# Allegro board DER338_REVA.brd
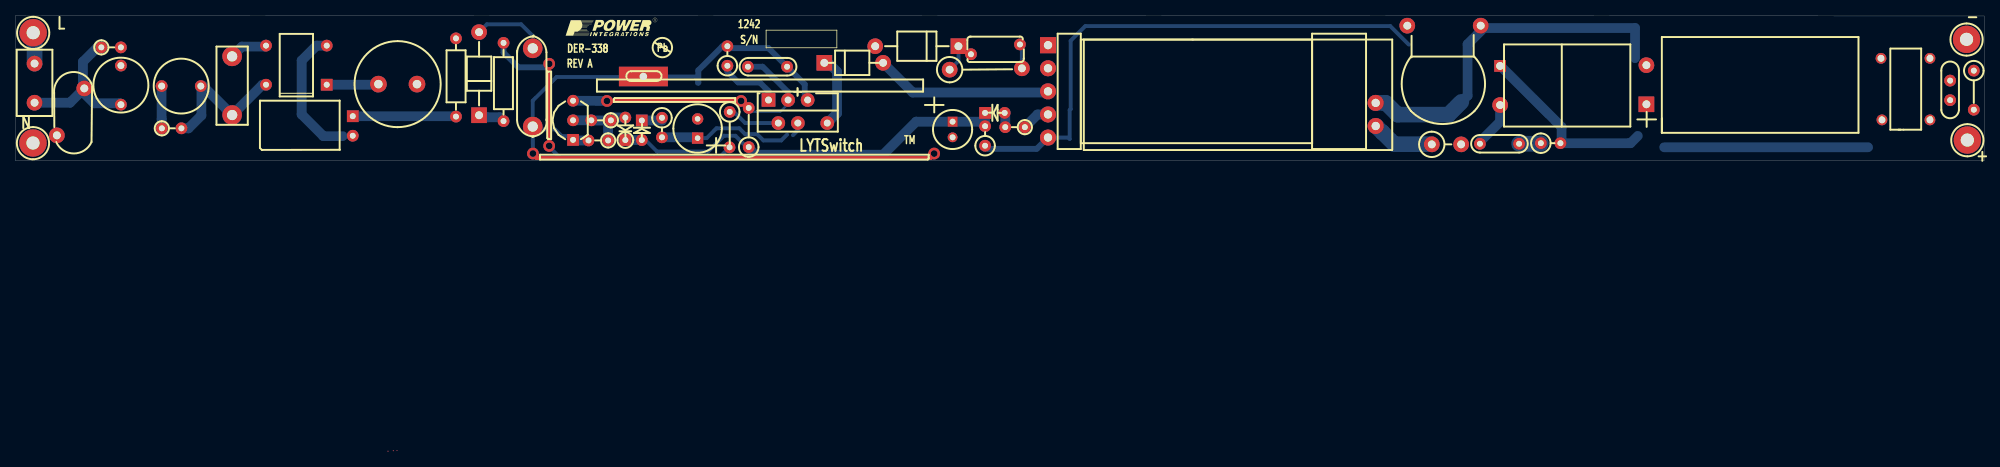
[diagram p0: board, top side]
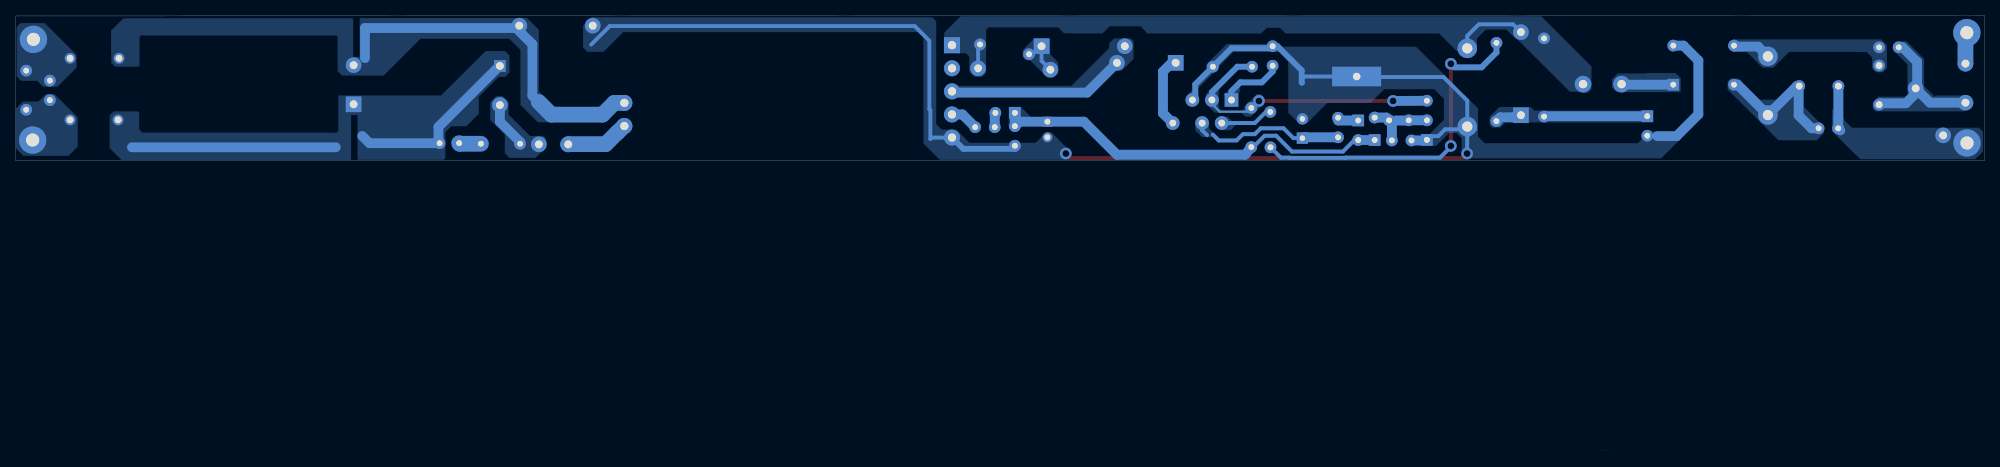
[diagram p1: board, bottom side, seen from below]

Outline 255.41 x 18.84 mm; copper layers: TOP, BOTTOM. Coordinates in mm from the lower left corner of the outline.
Outline path: 0.02,0 0,18.84 255.37,18.76 255.41,0 0.02,0 ; 0.02,0 0.04,0 0.02,0

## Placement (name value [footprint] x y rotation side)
BR1  DF06M  [PIDAXBRIDGEDFM]  40.4 9.86 270 top
C1  33 nF  [PI_NP_CAP400X160LS300D040]  28.11 13.51 270 top
C2  1 uF  [PIPOLCAPCYLD250LS100030]  43.76 5.74 270 top
C3  100 nF  [PINPCAPRAD500X260400040]  67.07 14.58 270 top
C4  2.2 nF  [PINPCAPRAD290X160250030]  130.29 15.06 180 top
C5  100 nF  [PINPCAPRAD200X100200030]  95.01 12.17 0 top
C6  47 uf  [PIPOLCAPCLYD248LS098028]  88.49 4.14 90 top
C7  10 uF  [PIPOLCAPCLYD200LS80030]  121.56 5.03 270 top
C8  2.2 nF  [PINPYCAPRAD540X290LS400040]  190.06 17.5 180 top
C9  150 pF  [PINPCAPRAD250X100200030]  195.04 2.16 180 top
C10  330 uF  [PIPOLCAPCLYD500LS2000401000LH]  211.55 7.29 90 top
C11  100 nF  [PINPCAPRAD200X100100030]  250.94 7.82 90 top
D1  1N4007  [PIDV200X110X040DO41]  60.14 5.87 90 top
D2  BYV26B  [PIDAX425X150040SOD57]  122.32 14.83 180 top
D3  UF4004  [PIDV200X110X040DO41#2]  103.78 12.67 0 top
D4  BAV21  [PIDV200X080X030DO35]  125.77 6.17 0 top
D5  1N4148  [PIDV200X080X030DO35]  81.25 5.18 270 top
D6  LQA06T300  [PI_TO220]  192.57 12.27 180 top
F1  3.15 A  [PI_RST_MICROFUSE]  2.48 12.57 270 top
HS1  HEATSINK,FAB, eSIP WITH BRKTS, DER318, PI CUST  [PI_HS_DER318_ESIP]  75.43 8.94 0 top
J1  CON1  [PITPKEYSTONE125X125]  2.3 16.59 0 top
J2  CON1  [PITPKEYSTONE125X125]  2.28 2.26 0 top
J3  CON1  [PITPKEYSTONE125X125]  253.18 2.64 0 top
J4  CON1  [PITPKEYSTONE125X125]  253.08 15.72 0 top
L1  1 mH  [PICHOKE030DIALS200035]  13.68 7.24 90 top
L2  1 mH  [PICHOKE030DIALS200035]  18.97 9.65 0 top
L3  470 uH  [PI_CHOKE_TOK441LS197D043]  47.08 9.91 0 top
L4  Ferrite Bead (3.5 x 4.45 mm)  [PI12WVRESD180LS150D040#2]  183.71 2.08 0 top
L5  100uH  [PI_TOROID_CM_CHOKE_4P]  238.04 3.1 0 top
NOREF  -  []  0.02 0.03 90 top
NOREF#2  -  []  0.02 0 0 top
NOREF#3  -  []  -244.17 -145.45 0 top
NOREF#4  -  []  -12.51 -112.42 0 top
NOREF#5  -  []  71.37 16.13 0 top
Q1  2N3904  [PITO92R100]  72.33 2.67 90 top
R1  5.1 k  [PI18WVRESD80LS100D030]  11.14 14.68 0 top
R2  5.1 k  [PI18WVRESD80LS100D030]  18.99 4.17 0 top
R4  200 k  [PI12WVRESD180LS150D040]  121.18 11.79 0 top
R5  1.5 M  [PI14WRESD100LS500D030]  63.31 5.11 90 top
R6  604 k  [PI14WVRESD100LS200D030]  92.65 6.3 270 top
R8  5.1 k  [PI14WVRESD100LS100D030]  83.86 5.54 270 top
R9  24.9 k  [PI14WVRESD100LS100D030]  92.35 12.29 90 top
R10  130 k  [PI14WVRESD100LS100D030#3]  95.11 1.73 90 top
R11  10 k  [PI14WVRESD100LS100D030]  125.77 1.91 90 top
R12  4.7 k  [PI18WVRESD80LS100D030]  76.88 2.59 180 top
R13  51  [PI18WVRESD80LS100D030]  130.93 4.32 180 top
R14  47  [PI14WVRESD100LS100D030]  197.86 2.24 0 top
R15  20 k  [PI14WVRESD100LS100D030#3]  254.02 11.66 270 top
R16  510 k  [PI14WVRESD100LS100D030#2]  57.14 15.85 270 top
R17  100  [PI18WVRESD80LS100D030]  77.23 5.21 180 top
RV1  140 Vac  [PIDISC350X225LS240X140040]  8.93 9.35 270 top
T1  EDR2810  [PI_BOBBIN_EDR2810_9P]  155.19 8.97 0 top
U1  LYT4215E  [PIICESIP76TH]  97.68 7.85 0 top
VR1  1N5256B  [PIDV200X080X030DO35#2]  79.11 2.64 90 top

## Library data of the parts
BR1 = DIODE BRIDGE_+-~~
C1 C3-C5 C9 C11 = CAP NP
C2 = CAP POL: alternate symbols: (pipolcapcyld250ls100030h)
C6 = CAP POL
C7 = CAP POL: alternate symbols: (pipolcapclyd200ls80030h)
C8 = CAP NP: alternate symbols: (pinpycaprad540x290ls400040h)
C10 = CAP POL: alternate symbols: (pipolcapclyd500ls2000401000lh)
D1 = DIODE: alternate symbols: (pidax475x125040do41,pidv200x110x040do41wbead,pidax390x125040do41)
D2 = DIODE: alternate symbols: (pidax425x150040sod57)
D3 = DIODE: alternate symbols: (pidax475x125040do41,pidax390x125040do41)
D4 D5 = DIODE: alternate symbols: (pidax375x070030do35,pidv100x080x030do35)
D6 = DIODE: alternate symbols: (PI_TO220)
F1 = FUSE
HS1 = HS-PI_CUSTOM
J1-J4 = TESTPOINT
L1-L4 = INDUCTOR
L5 = INDUCTOR_4P
Q1 = NPN_EBC: alternate symbols: (PIT092100)
R1 R2 = R: alternate symbols: (pi18wresd080ls300d030); tolerance: 5%
R4 = R: alternate symbols: (pi12wvresd180ls200d040,pi12wvresd180ls250d040,pi12wresd180ls675d040)
R5 R8 R11 R15 = R: alternate symbols: (pi14wvresd100ls200d030,pi14wresd100ls400d030,pi14wresd100ls500d030); tolerance: 5%
R6 R10 R14 R16 = R: alternate symbols: (pi14wvresd100ls200d030,pi14wresd100ls400d030,pi14wresd100ls500d030)
R9 = R: alternate symbols: (pi14wvresd100ls200d030,pi14wresd100ls400d030,pi14wresd100ls500d030); tolerance: 1%
R12 R13 R17 = R: alternate symbols: (pi18wresd080ls300d030)
RV1 = VARISTOR
T1 = BEDR2810_H_9P
U1 = LNK40X_eSIP
VR1 = DIODE_ZENER: alternate symbols: (pidax375x070030do35)

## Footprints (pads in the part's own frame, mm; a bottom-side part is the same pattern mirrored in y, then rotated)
PI12WVRESD180LS150D040
  round 2.032 hole 1.016: 1(0,0) 2(9.373,0.178)
PI12WVRESD180LS150D040#2
  round 2.032 hole 1.016: 1(0,0) 2(3.81,0)
PI14WRESD100LS500D030
  round 1.524 hole 0.762: 1(0,0) 2(10.16,0)
PI14WVRESD100LS100D030
  round 1.524 hole 0.762: 1(0,0) 2(2.54,0)
PI14WVRESD100LS100D030#2
  round 1.524 hole 0.762: 1(0,0) 2(10.16,0)
PI14WVRESD100LS100D030#3
  round 1.524 hole 0.762: 1(0,0) 2(5.08,0)
PI14WVRESD100LS200D030
  round 1.524 hole 0.762: 1(0,0) 2(4.597,-0.025)
PI18WVRESD80LS100D030
  round 1.524 hole 0.762: 1(0,0) 2(2.54,0)
PI_BOBBIN_EDR2810_9P
  rect 2.083x2.083 hole 1.067: 1(-21.25,5.999)
  round 2.083 hole 1.067: 2(-21.25,3) 3(-21.25,0) 4(-21.25,-3) 5(-21.25,-5.999) 6(21.25,-4.501) 7(21.25,-1.501)
  round 0.127 smd: 8(-106.172,-46.685) 9(-106.858,-46.736)
PI_CHOKE_TOK441LS197D043
  round 2.159 hole 1.092: 1(0,0) 2(5.001,0)
PI_HS_DER318_ESIP
  rect 6.35x2.54 hole 0.965: 1(6.02,1.956)
PI_NP_CAP400X160LS300D040
  round 2.54 hole 1.321: 1(0,0) 2(7.62,0)
PI_RST_MICROFUSE
  round 2.032 hole 1.016: 1(0,0) 2(5.08,0)
PI_TO220
  round 0.127 smd: (143.078,49.962)
  rect 1.524x1.524 hole 1.016: 1(0,0)
  round 2.032 hole 1.016: 2(0,5.08)
PI_TOROID_CM_CHOKE_4P
  round 1.397 hole 0.889: 1(4.064,2.159) 2(10.287,2.159) 3(10.287,10.16) 4(3.937,10.16)
PICHOKE030DIALS200035
  round 1.524 hole 0.889: 1(0,0) 2(5.08,0)
PIDAX425X150040SOD57
  rect 2.032x2.032 hole 1.016: 1(0,0)
  round 2.032 hole 1.016: 2(10.795,0)
PIDAXBRIDGEDFM
  rect 1.524x1.524 hole 0.762: 1(0.025,-0.025)
  round 1.524 hole 0.762: 2(-5.055,-0.025) 3(0.025,-7.899) 4(-5.055,-7.899)
PIDISC350X225LS240X140040
  round 2.032 hole 1.016: 1(0,0) 2(6.096,-3.556)
PIDV200X080X030DO35
  rect 1.524x1.524 hole 0.762: 1(0,0)
  round 1.524 hole 0.762: 2(2.54,0)
PIDV200X080X030DO35#2
  rect 1.524x1.524 hole 0.762: 1(0,0)
  round 1.524 hole 0.762: 2(2.921,0)
PIDV200X110X040DO41
  rect 2.032x2.032 hole 1.016: 1(0,0)
  round 2.032 hole 1.016: 2(10.795,0)
PIDV200X110X040DO41#2
  rect 2.032x2.032 hole 1.016: 1(1.143,0)
  round 2.032 hole 1.016: 2(8.763,0)
PIICESIP76TH
  rect 1.778x1.778 hole 0.889: 1(0,0)
  round 1.778 hole 0.889: 2(1.27,-2.997) 3(2.54,0) 4(3.81,-2.997) 5(5.08,0) 7(7.62,-2.997)
PINPCAPRAD200X100100030
  round 1.524 hole 0.762: 1(0,0) 2(2.54,0)
PINPCAPRAD200X100200030
  round 1.524 hole 0.762: 1(0,0) 2(5.08,0)
PINPCAPRAD250X100200030
  round 1.524 hole 0.762: 1(0,0) 2(5.08,0)
PINPCAPRAD290X160250030
  round 1.524 hole 0.762: 1(0,0) 2(6.35,1.27)
PINPCAPRAD500X260400040
  round 2.54 hole 1.321: 1(0.025,0.025) 2(10.185,0.025)
PINPYCAPRAD540X290LS400040
  round 2.032 hole 1.016: 1(0,0) 2(9.525,0)
PIPOLCAPCLYD200LS80030
  rect 1.27x1.27 hole 0.762: 1(0,0)
  round 1.27 hole 0.762: 2(2.032,0)
PIPOLCAPCLYD248LS098028
  rect 1.473x1.473 hole 0.711: 1(-1.25,0)
  round 1.473 hole 0.711: 2(1.25,0)
PIPOLCAPCLYD500LS2000401000LH
  rect 2.032x2.032 hole 1.016: 1(0,0)
  round 2.032 hole 1.016: 2(5.08,0)
PIPOLCAPCYLD250LS100030
  rect 1.524x1.524 hole 0.762: 1(0,0)
  round 1.524 hole 0.762: 2(2.54,0)
PITO92R100
  rect 1.524x1.524 hole 0.762: 1(0,0)
  round 1.524 hole 0.762: 2(2.54,0) 3(5.08,0)
PITPKEYSTONE125X125
  round 3.556 hole 1.702: 1(0,0)

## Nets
N1828072: J2.1 L2.1 R2.1 RV1.2
N2034514: R5.2 R6.2
N2034608: D3.1 U1.7(D)
N2034868: C5.1 Q1.3(COLLECTOR) R10.2 U1.3(FB)
N2034902: D2.2 D3.2 T1.3
N2034906: C2.1 D1.1 R5.1 R16.2
N2087372: BR1.3 C1.2 L2.2 R2.2
N2089046: C6.1 R8.2 U1.4(BP)
N2109142: F1.2 L1.1 R1.1 RV1.1
N2109297: BR1.4 C1.1 L1.2 R1.2
N2142347: BR1.2 C2.2 C3.2 C5.2 C6.2 C7.2 C8.2 HS1.1 Q1.1(EMITTER) R9.2 R11.1 R12.2 T1.5 U1.5(S)
N2216180: R13.1 T1.4
N2378865: F1.1 J1.1
N2448584: C7.1 D4.1 D5.2 R10.1 R11.2 VR1.1
N2451661: R9.1 U1.1(R)
N2492632: C10.1 D6.1 L5.1 R14.2
N2535639: C8.1 C10.2 L5.4 T1.7
N2539909: C11.1 J3.1 L5.2 R15.2
N2599685: D5.1 R8.1
N2869025: C3.1 C4.1 D1.2 L3.2 R4.2 R16.1 T1.1
N2871066: R6.1 U1.2(V)
N2889719: C4.2 D2.1 R4.1
N2895391: D4.2 R13.2
N2914407: BR1.1 L3.1
N2929446: R12.1 R17.1 VR1.2
N2934183: C11.2 J4.1 L5.3 R15.1
N2935852: C9.1 R14.1
N2971432: L4.1 T1.6
N2978816: C9.2 D6.2 L4.2
N2995553: Q1.2(BASE) R17.2

Pads without a net: T1 2 8 9

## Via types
v1: diameter 1.524, hole 0.889, TOP to BOTTOM, 6 vias

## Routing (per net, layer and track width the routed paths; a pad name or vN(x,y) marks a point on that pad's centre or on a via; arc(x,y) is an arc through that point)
N1828072: length 5.9
  BOTTOM w1.27: L2.1 18.97,5.38 R2.1 18.71,3.89
N2034514: length 43.5
  TOP w0.508: v1(69.23,1.88) v1(69.23,12.55)
  BOTTOM w0.508: R6.2 91.28,0.36 90.19,0.36 90.17,0.33 82.89,0.33 82.87,0.36 70.63,0.36 69.23,1.75 v1(69.23,1.88)
  BOTTOM w0.762: v1(69.23,12.55) 68.77,12.09 65.24,12.09 63.31,14.02 R5.2
N2034608: length 9.5
  BOTTOM w0.508: D3.1 104.79,12.8
  BOTTOM w1.27: D3.1 105.43,12.67 106.57,11.53 106.57,6.12 U1.7
N2034868: length 37
  TOP w0.508: v1(94.12,7.72) v1(76.73,7.72)
  BOTTOM w0.305: U1.3 99.84,7.47 99.84,6.96 99.2,6.32 95.39,6.32 R10.2
  BOTTOM w0.508: v1(94.12,7.72) R10.2
  BOTTOM w0.762: U1.3 100.22,8.86 96.92,12.17 C5.1
  BOTTOM w1.27: Q1.3 v1(76.73,7.72)
N2034902: length 23.1
  BOTTOM w1.27: T1.3 133.78,8.81 116.4,8.81 D3.2
N2034906: length 16.9
  BOTTOM w1.27: 60.11,5.89 D1.1 61.26,5.6 62.82,5.6 R5.1 ; R16.2 57.09,5.74 C2.1
N2087372: length 18.8
  BOTTOM w1.27: R2.2 22.45,4.17 24.12,5.84 24.12,9.58 L2.2 24.35,9.65 C1.2 32.05,9.83 BR1.3
N2089046: length 19.6
  BOTTOM w0.508: 100.86,3.28 101.49,3.91 U1.4 ; C6.1 89.65,2.89 90.92,4.17 93.9,4.17 94.66,3.4 96.21,3.4 97.02,2.59 99.33,2.59 100.09,3.35
  BOTTOM w1.27: C6.1 88.38,3 R8.2
N2109142: length 19.9
  BOTTOM w1.27: L1.1 13.5,7.42 10.2,7.42 8.93,8.69 RV1.1 ; RV1.1 8.75,9.53 8.75,12.8 10.63,14.68 R1.1 ; RV1.1 7.08,7.49 F1.2
N2109297: length 5
  BOTTOM w1.27: BR1.4 32.38,14.78 29.38,14.78 C1.1
N2142347: length 201.9
  TOP w0.508: v1(67.12,0.89) 67.56,0.3 118.71,0.3 v1(119.17,0.89)
  BOTTOM w0.254: 81.55,11.02 81.42,10.9
  BOTTOM w0.508: 81.53,10.9 81.46,10.83 70.18,10.83 67.1,7.75 C3.2 66.11,4.04 69.97,4.04 70.86,3.15 72.15,3.15 ; 81.53,10.9 HS1.1 81.42,10.9 ; 81.53,10.9 88.23,10.9 88.54,10.59 88.54,10.08 ; 67.1,3.66 v1(67.12,0.89) 66.97,0.64 66.97,0.79 ; 180.74,15.04 178.33,17.45 138.78,17.45 136.87,15.54 136.87,6.65 136.75,6.53 136.75,2.79 136.57,2.97 T1.5
  BOTTOM w0.762: 133.86,2.9 132.47,1.5 125.72,1.5 125.65,1.57 ; U1.5 102.38,8.23 102.38,9.88 C5.2 97.68,14.58 92.6,14.58 R9.2 91.71,14.83 88.58,11.7 88.58,10.13 88.54,10.08
  BOTTOM w1.27: BR1.2 39.06,14.91 37.13,12.98 37.13,5.97 39.95,3.15 42.44,3.15 ; 133.86,2.9 T1.5 ; v1(119.17,0.89) 119.14,0.9 ; R12.2 72.41,2.59 Q1.1 ; 67.1,3.66 C3.2
N2216180: length 3.7
  BOTTOM w1.27: T1.4 132.58,5.97 R13.1
N2378865: length 4.1
  BOTTOM w2.032: F1.1 2.48,16.41 J1.1
N2448584: length 53.6
  BOTTOM w0.508: R10.1 95.22,1.37 93.39,3.2 91.89,3.2 89.83,1.14 83.23,1.14 81.73,2.64 D5.2
  BOTTOM w1.27: R10.1 95.9,0.74 112.54,0.74 116.83,5.03 C7.1 125.19,5.03 R11.2 D4.1 ; VR1.1 D5.2
N2451661: length 8.3
  BOTTOM w0.762: R9.1 92.35,11.53 93.74,10.13 96.54,10.13 97.68,8.99 U1.1
N2492632: length 50.3
  BOTTOM w1.27: D6.1 192.63,12.27 200.55,4.34 200.55,2.39 R14.2 209.49,2.24 210.43,3.17 ; 240.3,1.7 213.86,1.7
N2535639: length 46.8
  BOTTOM w1.27: 210.08,13.28 210.08,17.2 190.47,17.2 188.36,15.09 188.36,8.41 187.55,7.59
  BOTTOM w2.032: 187.55,7.59 185.89,5.94 179.26,5.94 177.74,7.47 T1.7
N2599685: length 2.9
  BOTTOM w1.27: R8.1 83.84,5.18 D5.1
N2869025: length 12.8
  BOTTOM w0.508: C4.1 130.55,14.81 R4.2 ; C3.1 67.1,16.18 65.6,17.68 61.15,17.68 D1.2
N2871066: length 7
  BOTTOM w0.508: R6.1 93.21,6.3 94.66,4.85 U1.2
  BOTTOM w1.27: 92.52,6.3 R6.1
N2889719: length 3.7
  BOTTOM w0.508: 122.95,15.21 123.08,15.09 ; R4.1 122.32,12.93 D2.1
N2895391: length 2
  BOTTOM w1.27: R13.2 128.39,6.1 D4.2 128.23,6.26
N2914407: length 6.7
  BOTTOM w1.27: L3.1 47.01,9.83 BR1.1
N2929446: length 4.8
  BOTTOM w1.27: VR1.2 77.59,5.56 R17.1 76.88,4.85 R12.1
N2935852: length 2.9
  BOTTOM w2.032: C9.1 197.78,2.16 R14.1
N2971432: length 8.3
  BOTTOM w2.032: L4.1 183.68,2.11 178.86,2.11 177.36,3.61 177.33,3.61 176.47,4.47 T1.6
N2978816: length 6.1
  BOTTOM w1.27: C9.2 189.96,2.41 192.57,5.03 D6.2
N2995553: length 4
  BOTTOM w1.27: 76.34,5.18 74.69,5.18 ; R17.2 Q1.2

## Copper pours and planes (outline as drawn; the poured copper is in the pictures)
N1828072 on BOTTOM: 16.91,4.19 17.19,4.19 19.04,6.05 19.09,5.99 19.09,3.73 16.83,3.73 16.83,4.11
N1828072 on BOTTOM: 17.26,4.24 18.31,5.28 18.33,5.28 18.36,5.31 18.36,6.99 18.41,7.04 19.35,7.04 19.78,6.6 19.78,3.78 16.68,0.69 16.63,0.69 16.1,0.15 1.21,0.15 0.22,1.14 0.22,3.76 0.7,4.24
N2034868 on BOTTOM: 93.87,8.61 94.38,8.61 96.03,6.96 96.03,6.71 96.41,6.32 96.54,6.32 95.9,5.69 95.14,5.69 93.62,7.21 93.49,7.21 93.49,8.23
N2034868 on BOTTOM: 99.33,9.37 99.33,6.83 98.95,6.45 98.95,6.2 99.84,6.2 100.98,7.34 100.98,8.61 100.09,9.5 99.46,9.5
N2034902 on BOTTOM: 110.76,15.85 112.92,15.85 113.56,15.21 113.56,14.58 118.46,9.68 133.82,9.68 133.9,9.6 133.9,8.23 133.82,8.15 116.17,8.15 112.67,11.66 111.9,11.66 110.38,13.18 110.38,15.47
N2034906 on BOTTOM: 62.93,6.93 64.2,5.66 64.2,4.62 63.83,4.25 62.82,4.25 62.15,4.93 42.97,4.93 42.97,6.48 58.41,6.48 58.87,6.93
N2087372 on BOTTOM: 23.64,7.16 23.64,8.94 24.2,9.5 24.99,9.5 26.59,7.9 29.15,7.9 31.89,10.64 32.94,10.64 33.34,10.24 33.34,9.22 26.74,2.62 21.76,2.62 20.82,3.56 20.82,4.34
N2089046 on BOTTOM: 100.6,5.05 100.6,4.17 99.84,3.4 99.84,3.02 101.49,3.02 102.38,3.91 102.38,4.8 102.13,5.05
N2109142 on BOTTOM: 10.01,12.48 11.88,14.35 11.88,15.06 11.45,15.49 10.15,15.49 7.85,13.2 7.85,9.65 7.84,9.65 6.47,8.28 6.32,8.43 2.63,8.43 2.53,8.33 2.53,6.5 2.66,6.38 14.16,6.38 14.5,6.71 14.5,7.57 13.8,8.27 10.24,8.27 10.01,8.5
N2109297 on BOTTOM: 32.58,15.72 13.4,15.72 12.67,14.99 12.67,11.96 13.17,11.46 14.11,11.46 14.58,11.93 14.58,13.36 15.3,14.07 16.48,14.07 16.5,14.1 25.34,14.1 27.4,12.04 28.8,12.04 30.83,14.07 32.71,14.07 32.71,15.6
N2142347 on BOTTOM: 67.81,8.86 67.84,8.86 73.68,14.71 73.8,14.71 73.87,14.77 91.23,14.77 91.58,15.12 98.28,15.12 100.98,12.42 100.98,12.17 99.33,12.17 97.43,14.07 91.46,14.07 90.31,12.93 90.31,6.2 88.89,4.78 87.9,4.78 87.9,4.8 85.23,7.47 79.65,7.47 77.87,9.25 71.39,9.25 70.12,7.98 70.12,5.28 71.87,3.53 71.87,3.38 73.02,3.38 73.04,3.4 73.04,2.01 72.92,1.88 71.14,1.88 69.49,3.53 68.47,3.53 67.84,2.9 67.84,0.66 67.81,0.66 67.4,0.25 41.95,0.25 39.56,2.64 39.56,3.56 39.79,3.78 43.43,3.78 44.98,2.24 64.84,2.24 65.7,3.1 65.7,6.76
N2142347 on BOTTOM: 102.76,10.01 102.76,9.12 103.4,8.48 103.4,8.1 103.14,7.85 102.13,7.85 102,7.98 102,8.74 102.25,8.99 102.25,9.12 99.46,11.91 99.46,12.04 100.09,12.67 100.6,12.67 100.98,12.29 100.98,11.4 102.38,10.01
N2142347 on BOTTOM: 135.98,18.08 136.49,18.59 180.69,18.59 181.78,17.5 181.78,14.66 181.22,14.1 179.16,14.1 178.93,14.33 178.91,14.33 176.57,16.66 138.37,16.66 137.63,15.93 137.63,2.18 135.53,0.08 119.07,0.08 118.56,0.58 118.56,1.14 121.05,3.63 121.73,3.63 123.08,2.29 131.67,2.29 133.37,3.99 135.25,3.99 135.98,4.72
N2448584 on BOTTOM: 126.59,4.37 126.1,3.89 125.34,3.89 123.72,5.51 123.72,5.66 125.01,6.96 126.59,6.96
N2451661 on BOTTOM: 98.57,8.74 98.44,8.74 97.3,9.88 96.41,9.88 96.28,10.01 96.28,9.88 96.6,9.56 96.6,8.93 97.17,8.36 98.44,8.36 98.57,8.48
N2492632 on BOTTOM: 211.88,0.1 211.88,5.89 211.07,5.89 211.04,5.87 211.04,0.15 210.96,0.08 199.86,0.08 199.65,0.29 199.65,3.64 198.85,4.45 196.92,4.45 195.32,6.05 195.32,8.26 192.73,10.85 191.89,10.85 191.33,11.4 191.33,13.64 191.89,14.2 194.43,14.2 200.19,8.43 213.53,8.43 213.53,3.84 213.83,3.53 213.91,3.61 238.95,3.61 239.36,4.01 239.36,6.22 239.5,6.36 240.19,6.36 240.2,6.38 242.66,6.38 243.15,5.89 243.2,5.89 243.2,1.6 241.65,0.05 211.95,0.05 211.89,0.11
N2535639 on BOTTOM: 210.76,18.44 210.76,13.44 211.6,13.44 211.6,18.47 241.39,18.47 243.01,16.85 243.01,13.75 242.97,13.79 242.97,12.65 242.49,12.17 239.46,12.17 239.31,12.32 239.31,16.05 239.13,16.23 213.77,16.23 213.62,16.08 213.62,11.6 213.03,11.01 207.65,11.01 203.24,15.42 203.24,15.44 202.89,15.8 191.36,15.8 189.91,14.35 189.91,7.21 187.65,4.95 185.56,4.95 185.51,5 185.51,6.96 187.52,8.97 187.52,16.97 189.04,18.49 210.71,18.49
N2539909 on BOTTOM: 247.34,5.59 250.36,8.61 251.45,8.61 252.42,7.65 254.42,7.65 255.41,6.65 255.39,6.63 255.39,1.6 254.37,0.58 248.53,0.58 247.34,1.78
N2869025 on BOTTOM: 129.49,16.98 129.2,17.27 120.16,17.27 119.4,16.51 118.28,16.51 118.25,16.48 114.42,16.48 113.48,17.42 109.49,17.42 108.7,16.64 108.7,16.48 93.84,16.48 93.11,17.22 91.41,17.22 90.72,16.54 90.72,16.48 70.76,16.48 68.51,14.24 65.89,14.24 65.85,14.27 65.85,14.83 65.8,14.88 65.85,14.94 65.85,15.82 64.69,16.99 62.02,16.99 60.82,15.8 60.67,15.8 53.79,8.92 52.19,8.92 52.01,8.74 51.83,8.74 51.81,8.76 51.45,8.76 50.99,9.22 50.99,12.22 57.5,18.72 132.81,18.72 134.94,16.59 134.94,14.02 134.84,13.92 132.15,13.92 131.69,13.46 131.69,11.51 131.03,10.85 130.04,10.85 129.52,11.37 129.52,14.06 129.5,14.08 129.5,16.81 129.49,16.81
N2871066 on BOTTOM: 98.95,5.69 98.19,5.69 97.43,4.93 96.79,4.93 96.66,4.8 96.92,4.8 97.81,3.91 98.95,3.91 99.08,4.04 99.08,5.56
N2889719 on BOTTOM: 124.76,13.41 124.36,13.02 123.83,13.02 121.58,10.77 120.77,10.77 120.15,11.39 120.15,12.74 121.2,13.79 121.2,15.8 121.28,15.88 123.23,15.88 124.76,14.35
N2914407 on BOTTOM: 39.41,8.97 39.41,10.69 40.07,11.35 43.81,11.35 43.86,11.3 47.57,11.3 48.33,10.54 48.33,9.45 47.74,8.86 39.51,8.86
N2934183 on BOTTOM: 247.49,12.04 247.49,13.72 251.6,17.83 254.75,17.83 255.26,17.32 255.26,10.92 254.68,10.34 252.59,10.34 251.81,9.55 249.98,9.55
N2978816 on BOTTOM: 192.24,8.36 193.03,8.36 193.82,7.57 193.82,5.23 191.94,3.35 191.94,0.94 191.33,0.33 187.95,0.33 186.61,1.68 186.61,2.84 186.94,3.17 188.66,3.17 191.43,5.94 191.44,5.94 191.44,7.56

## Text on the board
Ref Des/Silkscreen Top: REV A | DER-338 | Pb | 1242 | S/N | TM | LYTSwitch | N | L | _ | +
PEN17: 13.  FR4 MATERIAL. 062 THICKNESS  1 LAYER. 2 OZ COPPER. | 14.  INSPECT BOARD FOR POSSIBLE WHISKERS. | PLEASE DELETTE THIS PIN | SLOT AT 3 PLACES
NCLEGEND-1-2: FIGURE | SIZE | 28.0 | 30.0 | 35.0 | 38.0 | 40.0 | 42.0 | 43.0 | 52.0 | 67.0 | DRILL CHART: TOP to BOTTOM | ALL UNITS ARE IN MILS | QTY | 2 | 53 | 14 | 6 | 1 | 20 | 7 | 4
